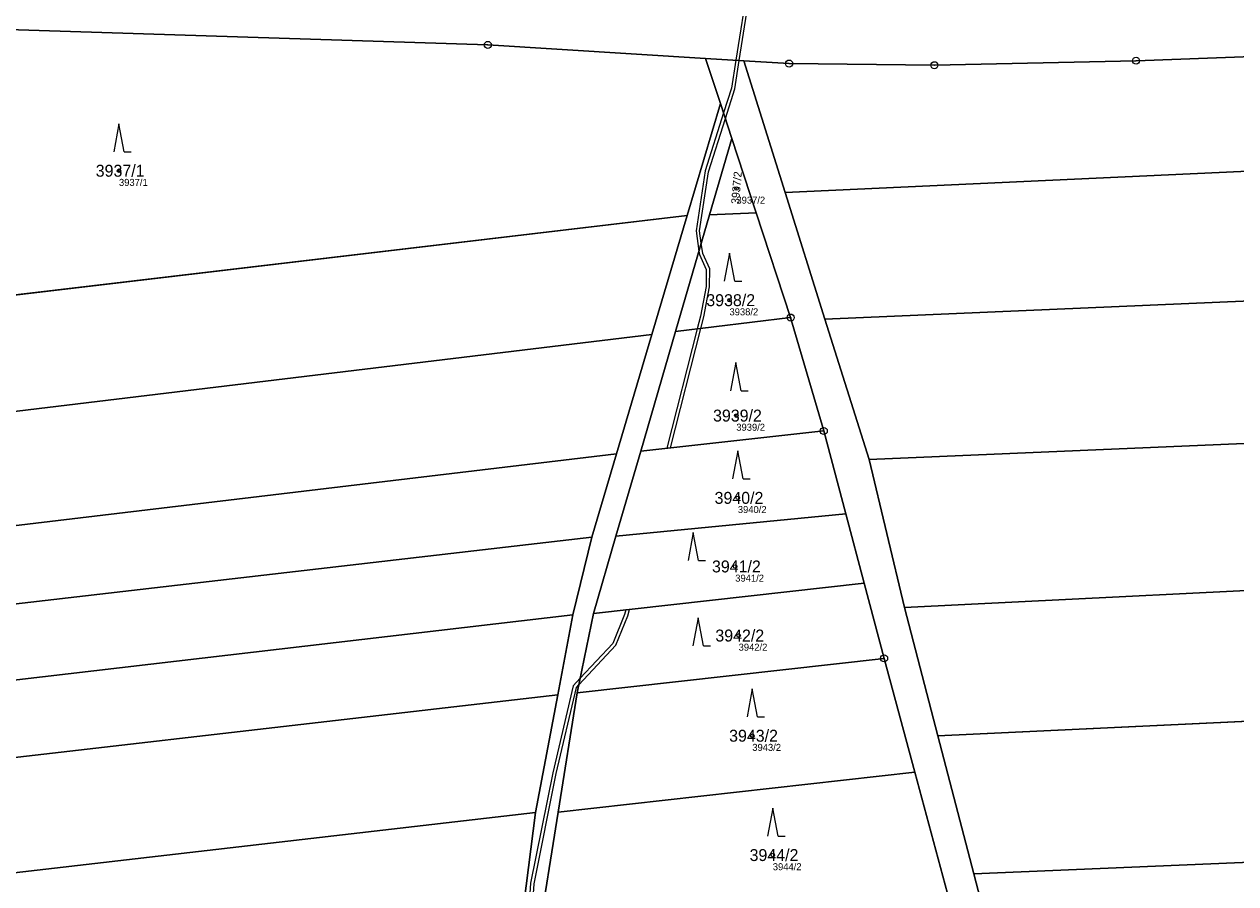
# Model space of a CAD drawing. Extents: x -658203 to -653176, y -1156738 to -1151709.
# Drawn here: x -657100.5 to -656928, y -1153863.2 to -1153740.7 of the extents above; entities that cross this region are included whole.
import ezdxf

# ---------------------------------------------------------------- set-up
doc = ezdxf.new("R2010")
doc.units = 0
for name, color, linetype in [('Vrstva 1', 7, 'Continuous'), ('Vrstva 13', 7, 'Continuous'), ('Vrstva 2', 7, 'Continuous'), ('Vrstva 3', 7, 'Continuous'), ('Vrstva 50', 7, 'Continuous'), ('Vrstva 51', 7, 'Continuous'), ('Vrstva 8', 7, 'Continuous')]:
    doc.layers.add(name, color=color, linetype=linetype)

msp = doc.modelspace()

# ---------------------------------------------------------------- linework, layer by layer
at = {"layer": 'Vrstva 1'}
for p, q in [((-657003.46, -1153745.58), (-657034.47, -1153743.66)), ((-657003.46, -1153745.58), (-657001.35, -1153752.02)), ((-656998.03, -1153745.92), (-657003.46, -1153745.58)), ((-656991.57, -1153746.32), (-656998.03, -1153745.92)), ((-656992.13, -1153764.68), (-656998.03, -1153745.92)), ((-657001.35, -1153752.02), (-657006.08, -1153767.99)), ((-657001.35, -1153752.02), (-656999.72, -1153756.98)), ((-657002.89, -1153767.86), (-656999.72, -1153756.98)), ((-656999.72, -1153756.98), (-656996.24, -1153767.59)), ((-656986.46, -1153782.72), (-656992.13, -1153764.68)), ((-657186.92, -1153789.35), (-657006.08, -1153767.99)), ((-657006.08, -1153767.99), (-657011.1, -1153784.92)), ((-657007.74, -1153784.51), (-657002.89, -1153767.86)), ((-657002.89, -1153767.86), (-656996.24, -1153767.59)), ((-656996.24, -1153767.59), (-656991.36, -1153782.5)), ((-657007.74, -1153784.51), (-656991.36, -1153782.5)), ((-656991.36, -1153782.5), (-656986.63, -1153798.66)), ((-656980.17, -1153802.73), (-656986.46, -1153782.72)), ((-657012.7, -1153801.53), (-657007.74, -1153784.51)), ((-657011.1, -1153784.92), (-657016.14, -1153801.91)), ((-656986.63, -1153798.66), (-657012.7, -1153801.53)), ((-656986.63, -1153798.66), (-656983.51, -1153810.44)), ((-657016.14, -1153801.91), (-657019.66, -1153813.79)), ((-657016.22, -1153813.64), (-657012.7, -1153801.53)), ((-656975.13, -1153823.82), (-656980.17, -1153802.73)), ((-657016.22, -1153813.64), (-656983.51, -1153810.44)), ((-656983.51, -1153810.44), (-656980.88, -1153820.36)), ((-657019.66, -1153813.79), (-657022.37, -1153824.83)), ((-657019.4, -1153824.64), (-657016.22, -1153813.64)), ((-657019.4, -1153824.64), (-656980.88, -1153820.36)), ((-656980.88, -1153820.36), (-656978.04, -1153831.05)), ((-656970.39, -1153842.07), (-656975.13, -1153823.82)), ((-656587.73, -1153824.04), (-656970.39, -1153842.07)), ((-657022.37, -1153824.83), (-657024.52, -1153836.26)), ((-657021.76, -1153835.98), (-657019.4, -1153824.64)), ((-657021.76, -1153835.98), (-656978.04, -1153831.05)), ((-656978.04, -1153831.05), (-656973.69, -1153847.26)), ((-657024.52, -1153836.26), (-657027.66, -1153853)), ((-657024.46, -1153852.98), (-657021.76, -1153835.98)), ((-656965.27, -1153861.76), (-656970.39, -1153842.07)), ((-657024.46, -1153852.98), (-656973.69, -1153847.26)), ((-656973.69, -1153847.26), (-656969.04, -1153864.56)), ((-657027.66, -1153853), (-657030.03, -1153871.31)), ((-657027.33, -1153871.1), (-657024.46, -1153852.98)), ((-656959.92, -1153882.38), (-656965.27, -1153861.76))]:
    msp.add_line(p, q, dxfattribs=at)
for points in [[(-657034.47, -1153743.66), (-657104.35, -1153741.42), (-657187.14, -1153737.59)], [(-656804.06, -1153739.8), (-656854.42, -1153742.66), (-656942.17, -1153745.92), (-656970.88, -1153746.56), (-656991.57, -1153746.32)], [(-656594.5, -1153744.02), (-656766.58, -1153754.27), (-656992.13, -1153764.68)], [(-656597.63, -1153764.18), (-656698.64, -1153770.35), (-656986.46, -1153782.72)], [(-657516.47, -1153840.78), (-657350.65, -1153825.04), (-657252.76, -1153813.29), (-657135.33, -1153799.93), (-657011.1, -1153784.92)], [(-656600.84, -1153784.89), (-656757.6, -1153793.22), (-656980.17, -1153802.73)], [(-657016.14, -1153801.91), (-657179.58, -1153821.45), (-657347.77, -1153840.3), (-657510.65, -1153855.71)], [(-656587.17, -1153803.13), (-656763.12, -1153813.28), (-656975.13, -1153823.82)], [(-657506.47, -1153866.44), (-657324.1, -1153849.07), (-657019.66, -1153813.79)], [(-657502.67, -1153876.19), (-657338.28, -1153860.87), (-657169.78, -1153842.07), (-657022.37, -1153824.83)], [(-657498.56, -1153886.73), (-657336.45, -1153871.26), (-657135.55, -1153849.08), (-657024.52, -1153836.26)], [(-656594.18, -1153844.89), (-656760.58, -1153853.12), (-656965.27, -1153861.76)], [(-657492.65, -1153901.89), (-657340.15, -1153887.94), (-657160.2, -1153868.33), (-657027.66, -1153853)]]:
    msp.add_lwpolyline(points, dxfattribs=at)
at = {"layer": 'Vrstva 13'}
for points in [[(-656997.42, -1153734.77), (-656999.16, -1153745.85), (-656998.66, -1153745.88), (-656996.95, -1153735.05), (-656996.71, -1153734.78)], [(-657004.07, -1153771.91), (-657004.32, -1153770.14), (-657003.05, -1153761.74), (-657000.64, -1153754.17), (-656999.3, -1153749.93), (-656998.66, -1153745.88), (-656999.16, -1153745.85), (-656999.78, -1153749.81), (-657000.91, -1153753.36), (-657003.53, -1153761.62), (-657004.82, -1153770.14), (-657004.41, -1153773.06)], [(-657004.66, -1153784.13), (-657004.12, -1153784.07), (-657003.69, -1153782.39), (-657002.89, -1153778.14), (-657002.87, -1153775.58), (-657003.86, -1153773.38), (-657004.07, -1153771.91), (-657004.41, -1153773.06), (-657004.34, -1153773.52), (-657003.37, -1153775.68), (-657003.39, -1153778.08), (-657004.19, -1153782.29)], [(-657008.44, -1153801.06), (-657004.12, -1153784.07), (-657004.66, -1153784.13), (-657008.98, -1153801.12)], [(-657021.52, -1153834.84), (-657016.26, -1153829.19), (-657014.52, -1153824.97), (-657014.29, -1153824.07), (-657014.83, -1153824.13), (-657015, -1153824.81), (-657016.68, -1153828.91), (-657021.33, -1153833.89)], [(-657045.26, -1153982.68), (-657044.38, -1153980.64), (-657044.06, -1153978.9), (-657041.23, -1153966.93), (-657038.72, -1153951.28), (-657035.76, -1153936), (-657033.1, -1153921.35), (-657030.66, -1153903.89), (-657027.89, -1153863.17), (-657024.73, -1153847.47), (-657021.85, -1153835.19), (-657021.52, -1153834.84), (-657021.33, -1153833.89), (-657022.31, -1153834.95), (-657025.23, -1153847.37), (-657028.39, -1153863.09), (-657031.16, -1153903.81), (-657033.6, -1153921.29), (-657036.26, -1153935.98), (-657039.22, -1153951.22), (-657041.73, -1153966.85), (-657044.56, -1153978.8)]]:
    msp.add_lwpolyline(points, close=True, dxfattribs=at)
at = {"layer": 'Vrstva 3'}
for p, q in [((-657086.99, -1153754.89), (-657087.74, -1153758.89)), ((-657086.24, -1153758.89), (-657086.99, -1153754.89)), ((-657086.24, -1153758.89), (-657085.24, -1153758.89)), ((-657000.06, -1153773.33), (-657000.81, -1153777.33)), ((-656999.31, -1153777.33), (-657000.06, -1153773.33)), ((-656999.31, -1153777.33), (-656998.31, -1153777.33)), ((-656999.15, -1153788.92), (-656999.9, -1153792.92)), ((-656998.4, -1153792.92), (-656999.15, -1153788.92)), ((-656998.4, -1153792.92), (-656997.4, -1153792.92)), ((-656998.87, -1153801.49), (-656999.62, -1153805.49)), ((-656998.12, -1153805.49), (-656998.87, -1153801.49)), ((-656998.12, -1153805.49), (-656997.12, -1153805.49)), ((-657005.21, -1153813.11), (-657005.96, -1153817.11)), ((-657004.46, -1153817.11), (-657005.21, -1153813.11)), ((-657004.46, -1153817.11), (-657003.46, -1153817.11)), ((-657004.52, -1153825.26), (-657005.27, -1153829.26)), ((-657003.77, -1153829.26), (-657004.52, -1153825.26)), ((-657003.77, -1153829.26), (-657002.77, -1153829.26)), ((-656996.81, -1153835.37), (-656997.56, -1153839.37)), ((-656996.06, -1153839.37), (-656996.81, -1153835.37)), ((-656996.06, -1153839.37), (-656995.06, -1153839.37)), ((-656993.89, -1153852.37), (-656994.64, -1153856.37)), ((-656993.14, -1153856.37), (-656993.89, -1153852.37)), ((-656993.14, -1153856.37), (-656992.14, -1153856.37))]:
    msp.add_line(p, q, dxfattribs=at)
at = {"layer": 'Vrstva 50'}
for centre in [(-657086.99, -1153761.59), (-656999.07, -1153764.12), (-657000.06, -1153780.03), (-656999.09, -1153796.47), (-656998.87, -1153808.19), (-656999.24, -1153817.96), (-656998.76, -1153827.8), (-656996.81, -1153842.07), (-656993.89, -1153859.07)]:
    msp.add_circle(centre, 0.25, dxfattribs=at)
at = {"layer": 'Vrstva 51'}
for points in [[(-656854.42, -1153742.66), (-656942.17, -1153745.92), (-656970.88, -1153746.56), (-656991.57, -1153746.32), (-656998.03, -1153745.92), (-656992.13, -1153764.68), (-656766.58, -1153754.27), (-656594.5, -1153744.02), (-656594.31, -1153742.79), (-656545.05, -1153751.58), (-656543.28, -1153725.51), (-656772.38, -1153740.09), (-656804.06, -1153739.8)], [(-657187.14, -1153737.59), (-657194.22, -1153737.32), (-657193.6, -1153741.73), (-657186.92, -1153789.35), (-657006.08, -1153767.99), (-657001.35, -1153752.02), (-657003.46, -1153745.58), (-657034.47, -1153743.66), (-657104.35, -1153741.42)], [(-656766.58, -1153754.27), (-656992.13, -1153764.68), (-656986.46, -1153782.72), (-656698.64, -1153770.35), (-656597.63, -1153764.18), (-656596.59, -1153757.48), (-656594.5, -1153744.02)], [(-656996.24, -1153767.59), (-656999.72, -1153756.98), (-657002.89, -1153767.86)], [(-656698.64, -1153770.35), (-656986.46, -1153782.72), (-656980.17, -1153802.73), (-656757.6, -1153793.22), (-656600.84, -1153784.89), (-656597.63, -1153764.18)], [(-657350.65, -1153825.04), (-657252.76, -1153813.29), (-657135.33, -1153799.93), (-657011.1, -1153784.92), (-657006.08, -1153767.99), (-657186.92, -1153789.35), (-657347.05, -1153807.75), (-657522.59, -1153825.07), (-657516.47, -1153840.78)], [(-657007.74, -1153784.51), (-656991.36, -1153782.5), (-656996.24, -1153767.59), (-657002.89, -1153767.86)], [(-656986.63, -1153798.66), (-656991.36, -1153782.5), (-657007.74, -1153784.51), (-657012.7, -1153801.53)], [(-657516.47, -1153840.78), (-657510.65, -1153855.71), (-657347.77, -1153840.3), (-657179.58, -1153821.45), (-657016.14, -1153801.91), (-657011.1, -1153784.92), (-657135.33, -1153799.93), (-657252.76, -1153813.29), (-657350.65, -1153825.04)], [(-656600.84, -1153784.89), (-656757.6, -1153793.22), (-656980.17, -1153802.73), (-656975.13, -1153823.82), (-656763.12, -1153813.28), (-656587.17, -1153803.13), (-656603.25, -1153800.45), (-656602.53, -1153795.81)], [(-656986.63, -1153798.66), (-657012.7, -1153801.53), (-657016.22, -1153813.64), (-656983.51, -1153810.44)], [(-657016.14, -1153801.91), (-657179.58, -1153821.45), (-657347.77, -1153840.3), (-657510.65, -1153855.71), (-657506.47, -1153866.44), (-657324.1, -1153849.07), (-657019.66, -1153813.79)], [(-656587.05, -1153821.86), (-656582.16, -1153808), (-656580.86, -1153804.18), (-656587.17, -1153803.13), (-656763.12, -1153813.28), (-656975.13, -1153823.82), (-656970.39, -1153842.07), (-656587.73, -1153824.04)], [(-656980.88, -1153820.36), (-656983.51, -1153810.44), (-657016.22, -1153813.64), (-657019.4, -1153824.64)], [(-657502.67, -1153876.19), (-657338.28, -1153860.87), (-657169.78, -1153842.07), (-657022.37, -1153824.83), (-657019.66, -1153813.79), (-657324.1, -1153849.07), (-657506.47, -1153866.44)], [(-656978.04, -1153831.05), (-656980.88, -1153820.36), (-657019.4, -1153824.64), (-657021.76, -1153835.98)], [(-656587.73, -1153824.04), (-656970.39, -1153842.07), (-656965.27, -1153861.76), (-656760.58, -1153853.12), (-656594.18, -1153844.89)], [(-657336.45, -1153871.26), (-657135.55, -1153849.08), (-657024.52, -1153836.26), (-657022.37, -1153824.83), (-657169.78, -1153842.07), (-657338.28, -1153860.87), (-657502.67, -1153876.19), (-657498.56, -1153886.73)], [(-656973.69, -1153847.26), (-656978.04, -1153831.05), (-657021.76, -1153835.98), (-657024.46, -1153852.98)], [(-657340.15, -1153887.94), (-657160.2, -1153868.33), (-657027.66, -1153853), (-657024.52, -1153836.26), (-657135.55, -1153849.08), (-657336.45, -1153871.26), (-657498.56, -1153886.73), (-657492.65, -1153901.89)], [(-656760.58, -1153853.12), (-656965.27, -1153861.76), (-656959.92, -1153882.38), (-656847.25, -1153877.66), (-656600.41, -1153865.36), (-656600.08, -1153863.93), (-656594.18, -1153844.89)], [(-656969.04, -1153864.56), (-656973.69, -1153847.26), (-657024.46, -1153852.98), (-657027.33, -1153871.1)], [(-657334.01, -1153904.13), (-657133.59, -1153883), (-657030.03, -1153871.31), (-657027.66, -1153853), (-657160.2, -1153868.33), (-657340.15, -1153887.94), (-657492.65, -1153901.89), (-657486.5, -1153917.66)]]:
    msp.add_lwpolyline(points, close=True, dxfattribs=at)
for points in [[(-657104.35, -1153741.42), (-657034.47, -1153743.66), (-657003.46, -1153745.58), (-656998.03, -1153745.92), (-656991.57, -1153746.32), (-656970.88, -1153746.56), (-656942.17, -1153745.92), (-656854.42, -1153742.66), (-656804.06, -1153739.8)], [(-656959.92, -1153882.38), (-656965.27, -1153861.76), (-656970.39, -1153842.07), (-656975.13, -1153823.82), (-656980.17, -1153802.73), (-656986.46, -1153782.72), (-656992.13, -1153764.68), (-656998.03, -1153745.92), (-657003.46, -1153745.58), (-657001.35, -1153752.02), (-656999.72, -1153756.98), (-656996.24, -1153767.59), (-656991.36, -1153782.5), (-656986.63, -1153798.66), (-656983.51, -1153810.44), (-656980.88, -1153820.36), (-656978.04, -1153831.05), (-656973.69, -1153847.26), (-656969.04, -1153864.56)], [(-657027.33, -1153871.1), (-657024.46, -1153852.98), (-657021.76, -1153835.98), (-657019.4, -1153824.64), (-657016.22, -1153813.64), (-657012.7, -1153801.53), (-657007.74, -1153784.51), (-657002.89, -1153767.86), (-656999.72, -1153756.98), (-657001.35, -1153752.02), (-657006.08, -1153767.99), (-657011.1, -1153784.92), (-657016.14, -1153801.91), (-657019.66, -1153813.79), (-657022.37, -1153824.83), (-657024.52, -1153836.26), (-657027.66, -1153853), (-657030.03, -1153871.31)]]:
    msp.add_lwpolyline(points, dxfattribs=at)
at = {"layer": 'Vrstva 8'}
for centre, radius in [((-657034.47, -1153743.66), 0.5), ((-657034.47, -1153743.66), 0.0303), ((-656991.57, -1153746.32), 0.5), ((-656991.57, -1153746.32), 0.0303), ((-656970.88, -1153746.56), 0.5), ((-656970.88, -1153746.56), 0.0303), ((-656942.17, -1153745.92), 0.5), ((-656942.17, -1153745.92), 0.0303), ((-656991.36, -1153782.5), 0.5), ((-656991.36, -1153782.5), 0.0303), ((-656986.63, -1153798.66), 0.5), ((-656986.63, -1153798.66), 0.0303), ((-656978.04, -1153831.05), 0.5), ((-656978.04, -1153831.05), 0.0303)]:
    msp.add_circle(centre, radius, dxfattribs=at)

# ---------------------------------------------------------------- texts
at = {"layer": 'Vrstva 2'}
for s, p in [('3937/1', (-657090.3, -1153762.44)), ('3938/2', (-657003.36, -1153780.88)), ('3939/2', (-657002.4, -1153797.32)), ('3940/2', (-657002.18, -1153809.04)), ('3941/2', (-657002.55, -1153818.81)), ('3942/2', (-657002.07, -1153828.65)), ('3943/2', (-657000.11, -1153842.92)), ('3944/2', (-656997.2, -1153859.92))]:
    msp.add_text(s, height=1.7, dxfattribs=at).set_placement(p)
msp.add_text('3937/2', height=1.14, rotation=85, dxfattribs=at).set_placement((-656998.7, -1153766.38))
at = {"layer": 'Vrstva 50'}
for s, p in [('3937/1', (-657086.99, -1153763.75)), ('3937/2', (-656999.07, -1153766.28)), ('3938/2', (-657000.06, -1153782.19)), ('3939/2', (-656999.09, -1153798.63)), ('3940/2', (-656998.87, -1153810.35)), ('3941/2', (-656999.24, -1153820.12)), ('3942/2', (-656998.76, -1153829.96)), ('3943/2', (-656996.81, -1153844.23)), ('3944/2', (-656993.89, -1153861.23))]:
    msp.add_text(s, height=1, dxfattribs=at).set_placement(p)

doc.saveas('drawing.dxf')
